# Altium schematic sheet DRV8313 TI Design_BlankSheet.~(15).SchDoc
size 431 x 279 mm; Date: Not shown in title block; ApprovedBy: Not shown in title block; CheckedBy: Not shown in title block; Author: Not shown in title block; CompanyName: Not shown in title block; Engineer: Not shown in title block; Organization: Not shown in title block; Address1: Not shown in title block; Address2: Not shown in title block; Address3: Not shown in title block; Address4: Not shown in title block; DocumentNumber: 1; Revision: Use project parameter SCH_Rev; SheetNumber: 2; SheetTotal: 3; PageSetup: Record=PageOptions¦CenterHorizontal=True¦CenterVertical=True¦PrintScale=1.00¦XCorrection=1.00¦YCorrection=1.00¦PrintKind=0¦BorderSize=5000000¦LeftOffset=0¦BottomOffset=0¦Orientation=2¦PaperLength=1000¦PaperWidth=1000¦Scale=100¦PaperSource=15¦PrintQuality=600¦MediaType=1¦DitherType=10¦PaperKind=Letter¦PrintScaleMode=1
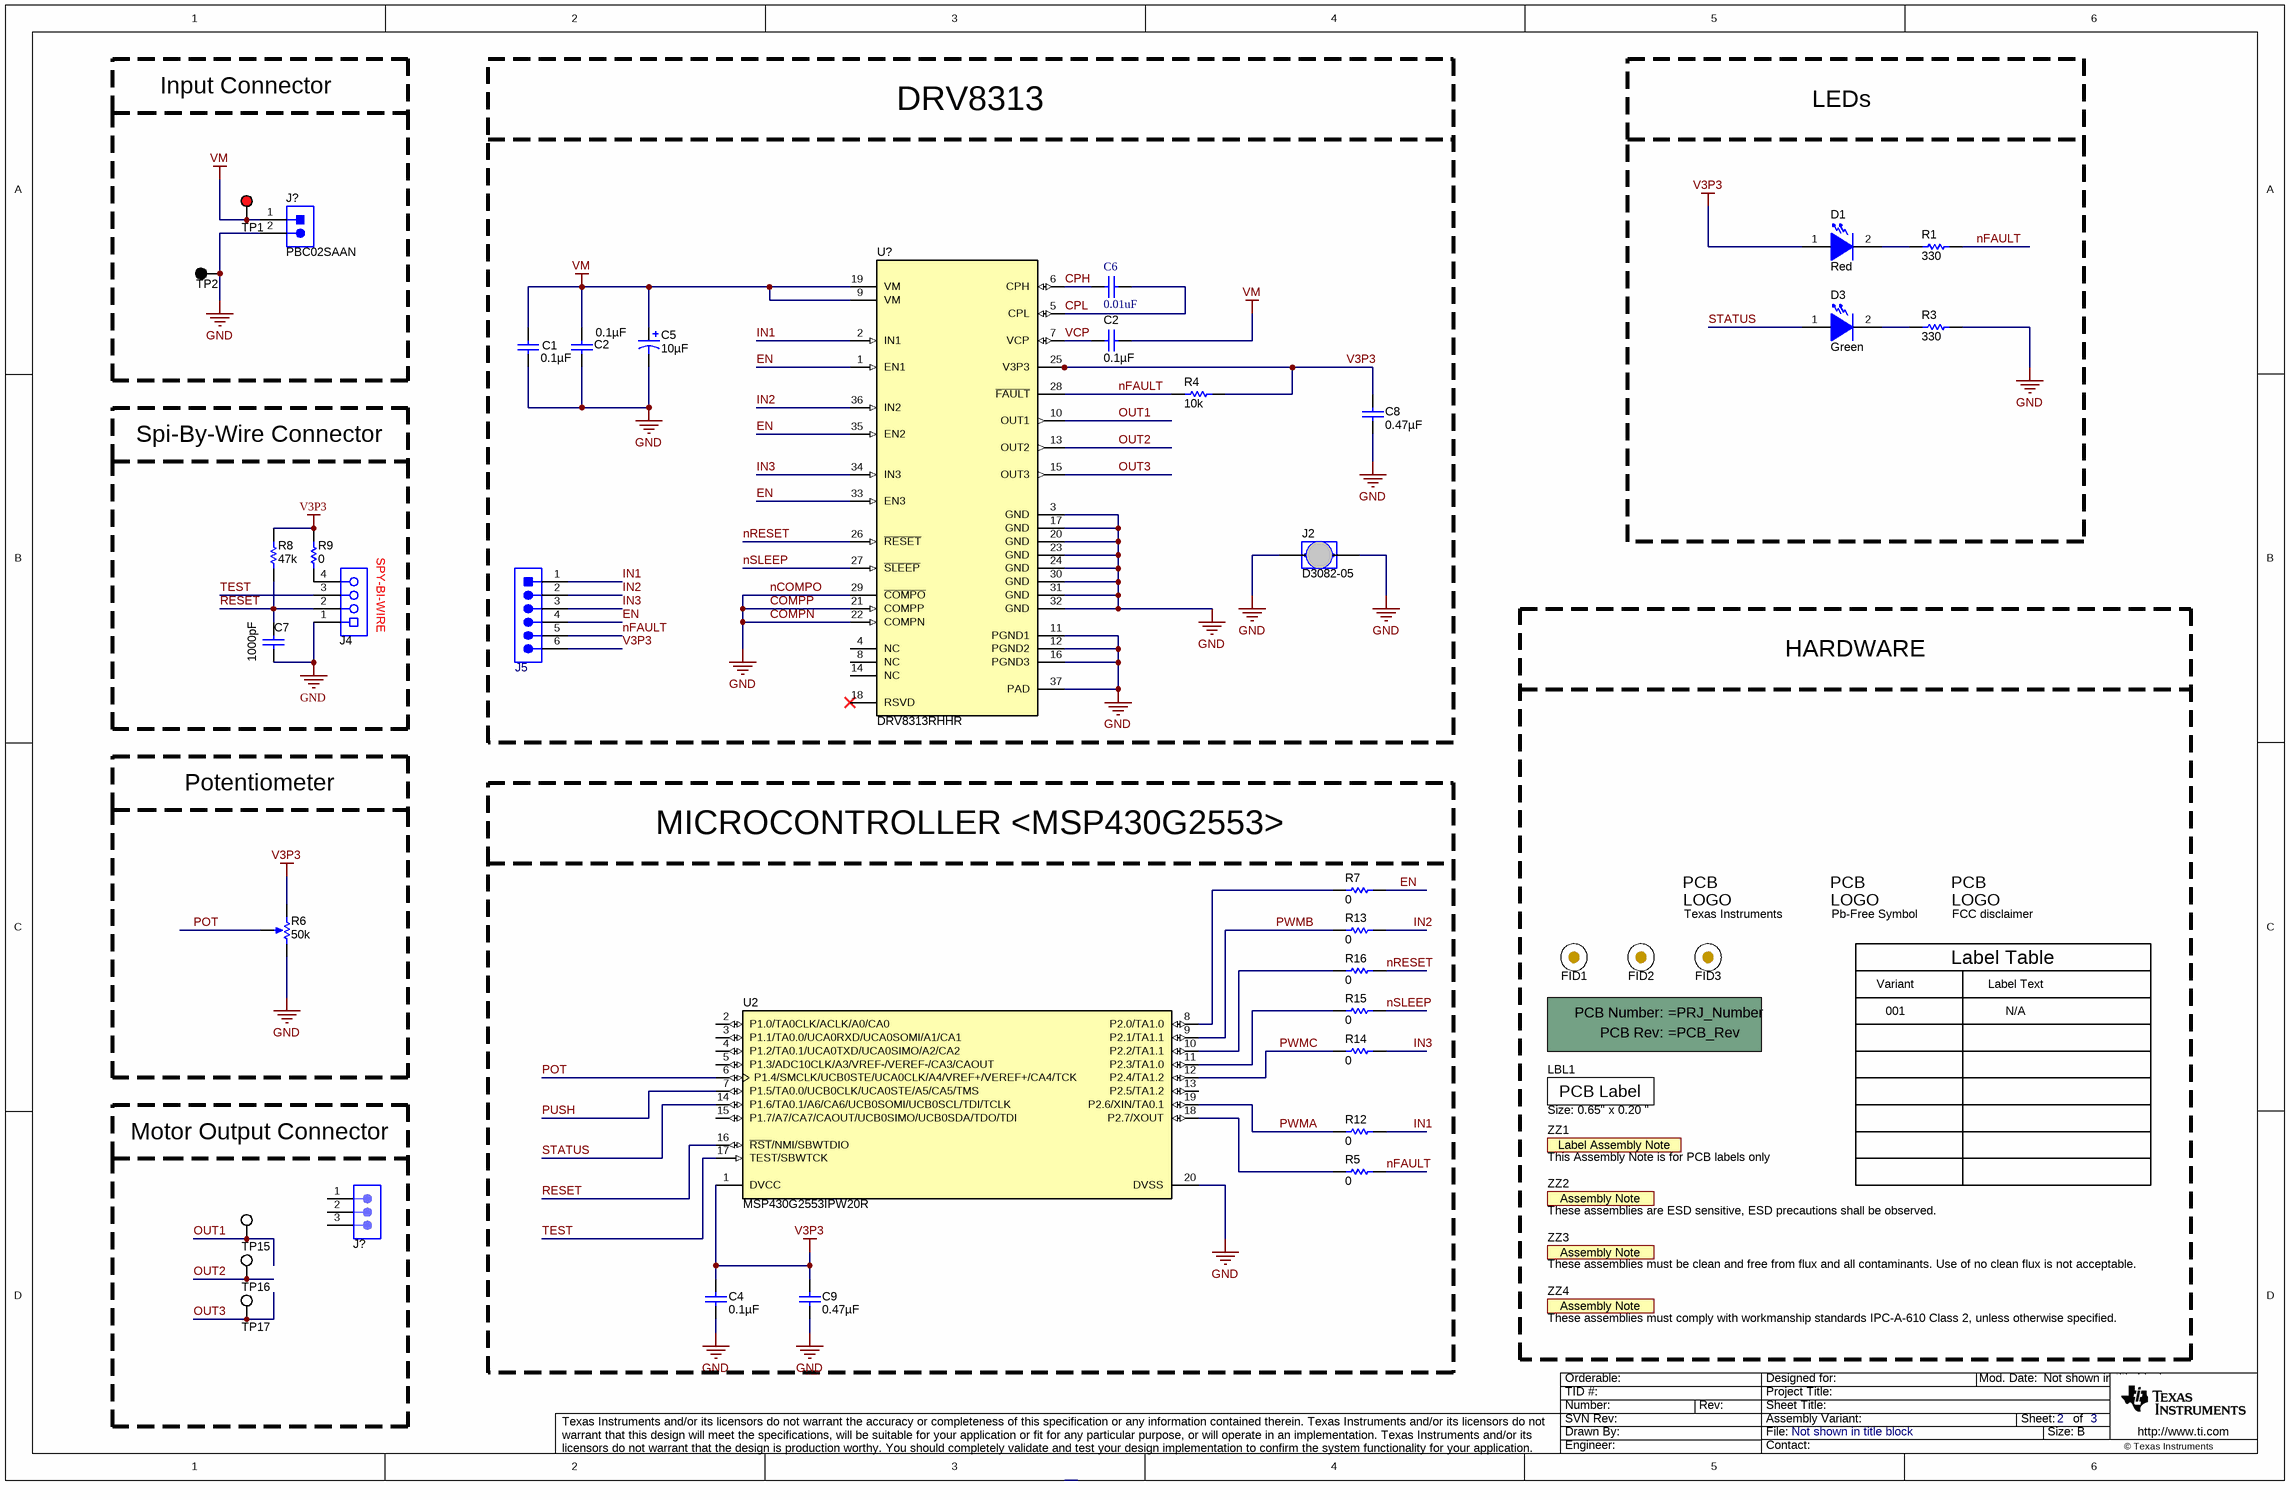
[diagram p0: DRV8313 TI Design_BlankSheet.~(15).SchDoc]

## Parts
(Parts that share a designator on the sheet are numbered #1, #2 ... from top to bottom, then left to right.)
!PCB  Printed Circuit Board  (value not drawn)  (mechanical)
C1  ValueDisplayed: 0.1µF  [0805_HV]  (hidden comment: C2012X5R2A104K125AA)
C2#1  ValueDisplayed: 0.1µF  [0805_HV]  (hidden comment: C2012X5R2A104K125AA)
C2#2  ValueDisplayed: 0.1µF  [0805_HV]  (hidden comment: C2012X5R2A104K125AA)
C4  ValueDisplayed: 0.1µF  [0603L]  (hidden comment: C0603C104K8RACTU)
C5  ValueDisplayed: 10µF  [SM_RADIAL_D8]  (hidden comment: EEE-FK1K100XP)
C6  0.01uF  [0603]
C7  ValueDisplayed: 1000pF  [0603L]  (hidden comment: GRM188R71C102KA01D)
C8  ValueDisplayed: 0.47µF  [0603]  (hidden comment: GCM188R71C474KA55D)
C9  ValueDisplayed: 0.47µF  [0603]  (hidden comment: GCM188R71C474KA55D)
D1  value Red  [LED_LTST-C170_Red]  (hidden comment: LTST-C170KRKT)
D3  value Green  [LTST-C170KGKT_Green]  (hidden comment: LTST-C170KGKT)
FID1  Fiducial  [Fiducial10-20]  (value not drawn)
FID2  Fiducial  [Fiducial10-20]  (value not drawn)
FID3  Fiducial  [Fiducial10-20]  (value not drawn)
J2  D3082-05  [Harwin_D3082-05]
J4  851-43-004-20-001000  [CONN_851-43-004-20-001000]  (value not drawn)
J5  PEC06SAAN  [Sullins_PEC06SAAN]  (value not drawn)
J?#1  PBC02SAAN  [Sullins_PBC02SAAN]
J?#2  PBC03SAAN  [PBC03SAAN]  (value not drawn)
LBL1  Size: 0.65" x 0.20 "  [Label_650x200]
Logo1  Texas Instruments  [TI_Stacked_Overlay_Small]  (no BOM)
Logo2  Pb-Free Symbol  [Pb-Free_Overlay_Small]  (no BOM)
Logo3  FCC disclaimer  [FCC_disclaimer]  (no BOM)
R1  ValueDisplayed: 330  [0603]  (hidden comment: CRCW0603330RJNEA)
R3  ValueDisplayed: 330  [0603]  (hidden comment: CRCW0603330RJNEA)
R4  ValueDisplayed: 10k  [0805_HV]  (hidden comment: CRCW080510K0JNEA)
R5  ValueDisplayed: 0  [0805_HV]  (hidden comment: ERJ-6GEY0R00V)
R6  value 50k  [Bourns_3352T]  (hidden comment: 3352T-1-503LF)
R7  ValueDisplayed: 0  [0805_HV]  (hidden comment: ERJ-6GEY0R00V)
R8  value 47k  [0603L]  (hidden comment: CRCW060347K0JNEA)
R9  value 0  [0603L]  (hidden comment: CRCW06030000Z0EA)
R12  ValueDisplayed: 0  [0805_HV]  (hidden comment: ERJ-6GEY0R00V)
R13  ValueDisplayed: 0  [0805_HV]  (hidden comment: ERJ-6GEY0R00V)
R14  ValueDisplayed: 0  [0805_HV]  (hidden comment: ERJ-6GEY0R00V)
R15  ValueDisplayed: 0  [0805_HV]  (hidden comment: ERJ-6GEY0R00V)
R16  ValueDisplayed: 0  [0805_HV]  (hidden comment: ERJ-6GEY0R00V)
TP1  5000  [Keystone5000]  (value not drawn)
TP2  5001  [Keystone5001]  (value not drawn)
TP15  5002  [Keystone5002]  (value not drawn)
TP16  5002  [Keystone5002]  (value not drawn)
TP17  5002  [Keystone5002]  (value not drawn)
U2  MSP430G2553IPW20R  [PW0020A_N]
U?  DRV8313RHHR  [RHH0036C]
ZZ1  This Assembly Note is for PCB labels only  [AssemblyNoteLabel]  (no BOM)
ZZ2  These assemblies are ESD sensitive, ESD precautions shall be observed.  [AssemblyNote]  (no BOM)
ZZ3  These assemblies must be clean and free from flux and all contaminants. Use of no clean flux is not acceptable.  [AssemblyNote]  (no BOM)
ZZ4  These assemblies must comply with workmanship standards IPC-A-610 Class 2, unless otherwise specified.  [AssemblyNote]  (no BOM)

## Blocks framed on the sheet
DRV8313: C1 C2#1 C2#2 C5 C6 C8 J2 J5 R4 U?
SPY-BI-WIRE: C7 J4 R8 R9
HARDWARE: !PCB FID1-FID3 LBL1 Logo1-Logo3 ZZ1-ZZ4

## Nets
COMPN: C1.1 C2#2.2 C4.2 C5.2(-) C7.2 C8.2 C9.2 J2.1 J2.2 J4.1 J?#1.2 R3.2 R6.3(CW) TP2.1 U2.20(DVSS) U?.3(GND) U?.11(PGND1) U?.12(PGND2) U?.16(PGND3) U?.17(GND) U?.20(GND) U?.21(COMPP) U?.22(COMPN) U?.23(GND) U?.24(GND) U?.29(~{COMPO}) U?.30(GND) U?.31(GND) U?.32(GND) U?.37(PAD)  [also labelled COMPP, GND, nCOMPO]
V3P3: C4.1 C8.1 C9.1 D1.1(A) J5.6 R4.2 R6.1(CCW) R8.2 R9.2 U2.1(DVCC) U?.25(V3P3)
VM: C1.2 C2#1.2 C2#2.1 C5.1(+) J?#1.1 TP1.1 U?.9(VM) U?.19(VM)
CPH: C6.2 U?.6(CPH)
CPL: C6.1 U?.5(CPL)
EN: J5.4 R7.2 U?.1(EN1) U?.33(EN3) U?.35(EN2)
IN1: J5.1 R12.2 U?.2(IN1)
IN2: J5.2 R13.2 U?.36(IN2)
IN3: J5.3 R14.2 U?.34(IN3)
nFAULT: J5.5 R1.2 R4.1 R5.2 U?.28(~{FAULT})
nRESET: R16.2 U?.26(~{RESET})
nSLEEP: R15.2 U?.27(~{SLEEP})
OUT1: TP15.1 U?.10(OUT1)
OUT2: TP16.1 U?.13(OUT2)
OUT3: TP17.1 U?.15(OUT3)
POT: R6.2(WIPER) U2.6(P1.4/SMCLK/UCB0STE/UCA0CLK/A4/VREF+/VEREF+/CA4/TCK)
PUSH: U2.7(P1.5/TA0.0/UCB0CLK/UCA0STE/A5/CA5/TMS)
PWMA: R12.1 U2.19(P2.6/XIN/TA0.1)
PWMB: R13.1 U2.9(P2.1/TA1.1)
PWMC: R14.1 U2.12(P2.4/TA1.2)
RESET: C7.1 J4.2 R8.1 U2.16(~{RST}/NMI/SBWTDIO)
STATUS: D3.1(A) U2.14(P1.6/TA0.1/A6/CA6/UCB0SOMI/UCB0SCL/TDI/TCLK)
TEST: J4.3 U2.17(TEST/SBWTCK)
VCP: C2#1.1 U?.7(VCP)
NetD1_2: D1.2(K) R1.1
NetD3_2: D3.2(K) R3.1
NetJ4_4: J4.4 R9.1
NetR5_1: R5.1 U2.18(P2.7/XOUT)
NetR7_1: R7.1 U2.8(P2.0/TA1.0)
NetR15_1: R15.1 U2.11(P2.3/TA1.0)
NetR16_1: R16.1 U2.10(P2.2/TA1.1)

Not connected (* = marked no-connect by the designer): J?#2 1 2 3; U2 2(P1.0/TA0CLK/ACLK/A0/CA0) 3(P1.1/TA0.0/UCA0RXD/UCA0SOMI/A1/CA1) 4(P1.2/TA0.1/UCA0TXD/UCA0SIMO/A2/CA2) 5(P1.3/ADC10CLK/A3/VREF-/VEREF-/CA3/CAOUT) 13(P2.5/TA1.2) 15(P1.7/A7/CA7/CAOUT/UCB0SIMO/UCB0SDA/TDO/TDI); U? 4(NC) 8(NC) 14(NC) 18(RSVD)*

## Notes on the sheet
- Input Connector
- LEDs
- Spi-By-Wire Connector
- Potentiometer
- MICROCONTROLLER <MSP430G2553>
- Label Table
- Variant
- 001
- Label Text
- N/A
- Motor Output Connector

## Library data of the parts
!PCB = PCB: Manufacturer: Any; SymbolCreator: a0412235
C1 C2#1 C2#2 = C2012X5R2A104K125AA: CAP, CERM, 0.1 µF, 100 V, +/- 10%, X5R, 0805; Manufacturer: TDK; Polarized: N; CompType: Capacitor; Value: 0.1uF; U/M: EA; Cap_F: 0.0000001; Tolerance_%: 10; ESR_ohm: 0.020726; Value1: 0.020726 ohm; VDC_V: 100; Value2: 100V; IRMS_A: 1.456; TaMin_C: -55; TaMax_C: 85; Cap_Case: 0805; SizeArea_mm2: 2.5; SizeAreaWB_mm2: 6.75; SizeX_mm: 2; SizeY_mm: 1.25; SizeZ_mm: 1.45; AEC Category: Q200
C4 = C0603C104K8RACTU: CAP, CERM, 0.1 µF, 10 V, +/- 10%, X7R, 0603; Manufacturer: Kemet; Polarized: N; CompType: Capacitor; Value: 0.1uF; U/M: EA; Cap_F: 0.0000001; Tolerance_%: 10; Value1: Unknown; Value2: 10V; TaMin_C: -55; TaMax_C: 125; Cap_Case: 0603; AEC Category: Q200
C5 = EEE-FK1K100XP: CAP, AL, 10 µF, 80 V, +/- 20%, 2.4 ohm, AEC-Q200 Grade 2, SMD; Manufacturer: Panasonic; Polarized: Y; CompType: Capacitor; Value: 10uF; U/M: EA; Cap_F: 0.00001; Tolerance_%: 20; Value1: 2.4 ohm; VDC_V: 80; Value2: 80V; ESR_ohm: 2.4; IRMS_A: 0.06; TaMin_C: -55; TaMax_C: 105; Cap_Case: D8; SizeAreaWB_mm2: 84.28; SizeArea_mm2: 51.48; SizeX_mm: 7.8; SizeY_mm: 6.6; SizeZ_mm: 7.7; AEC Category: Q200; AEC Grade: 2
C6 = Cap: Capacitor; Manufacturer: Murata; MFG Part Number: GCM188R72A103KA37D; Value: .01uF; Cap Voltage: 100V
C7 = GRM188R71C102KA01D: CAP, CERM, 1000 pF, 16 V, +/- 10%, X7R, 0603; Manufacturer: MuRata; Polarized: N; CompType: Capacitor; Value: 1000pF; U/M: EA; Cap_F: 0.000000001; Tolerance_%: 10; Value1: Unknown; VDC_V: 16; Value2: 16V; TaMin_C: -55; TaMax_C: 125; Cap_Case: 0603; AEC Category: Q200
C8 C9 = GCM188R71C474KA55D: CAP, CERM, 0.47 µF, 16 V, +/- 10%, X7R, AEC-Q200 Grade 1, 0603; Manufacturer: MuRata; Polarized: N; CompType: Capacitor; Value: 0.47uF; U/M: EA; Cap_F: 0.00000047; Tolerance_%: 10; Value1: Unknown; VDC_V: 16; Value2: 16V; TaMin_C: -55; TaMax_C: 125; SizeArea_mm2: 1.28; SizeAreaWB_mm2: 4.68; SizeX_mm: 1.6; SizeY_mm: 0.8; SizeZ_mm: 1; AEC Category: Q200; AEC Qualified: Y
D1 = LTST-C170KRKT: LED, Red, SMD; Manufacturer: Lite-On; Type: AlInGaP; Vf_V: 2; Value2: 2V; Io_A: 0.02; Value1: W; SizeAreaWB_mm2: 6.75; SizeArea_mm2: 2.5; SizeY_mm: 1.25; SizeZ_mm: 1.2; U/M: EA
D3 = LTST-C170KGKT: LED, Green, SMD; Manufacturer: Lite-On; Type: AlInGaP; Vf_V: 2; Value2: 2V; Io_A: 0.02; Value1: W; U/M: EA
FID1-FID3 = Fiducial: Fiducial mark.  There is nothing to buy or mount.; SymbolCreator: codlsc
J2 = D3082-05: 1mm Uninsulated Shorting Plug, 10.16mm spacing, TH; Manufacturer: Harwin; SymbolCreator: a0799628; CompType: Jumper Wire
J4 = 851-43-004-20-001000: SOCKET .050" GRID SIP 4 POS R/A, TH; Manufacturer: Mill-Max; SymbolCreator: a0411947; CompType: Header
J5 = PEC06SAAN: Header, 100mil, 6x1, Tin, TH; Manufacturer: Sullins Connector Solutions; SymbolCreator: a0412235; U/M: EA
J?#1 = PBC02SAAN: Header, 100mil, 2x1, Gold, TH; Manufacturer: Sullins Connector Solutions; SymbolCreator: a0412235; Pitch_mm: 2.54; Gender: Male; Shrouded: N; Row_Count: 1; Current_A: 3; Voltage_V: 1800; Cert_UL: Y
J?#2 = PBC03SAAN: Header, 100mil, 3x1, Gold, TH; Manufacturer: Sullins Connector Solutions
LBL1 = THT-14-423-10: Thermal Transfer Printable Labels, 0.650" W x 0.200" H - 10,000 per roll; Manufacturer: Brady; SymbolCreator: a0412235; CompType: Label
Logo1 = TI_Logo: Texas Instrument Corporate Signature; SymbolCreator: codlsc
Logo2 = Pb-Free: SymbolCreator: a0412235
Logo3 = FCC_disclaimer: SymbolCreator: codlsc
R1 R3 = CRCW0603330RJNEA: RES, 330, 5%, 0.1 W, 0603; Manufacturer: Vishay-Dale; CompType: Resistor; Value: 330; Value_Code: 330R; Tolerance_%: 5; Power_W: 0.1; Value2: 0.1W; VDC_V: 75; TempCo: 200 ppm/C; SizeArea_mm2: 1.28; SizeX_mm: 1.6; SizeY_mm: 0.8; SizeZ_mm: 1; EIA_Code: E24; U/M: EA; AEC Category: Q200
R4 = CRCW080510K0JNEA: RES, 10 k, 5%, 0.125 W, 0805; Manufacturer: Vishay-Dale; CompType: Resistor; Value: 10k; Res_ohm: 10000; Value_Code: 10k0; Tolerance_%: 5; Power_W: 0.125; Value2: 0.125W; VDC_V: 150; TempCo: 200 ppm/C; SizeArea_mm2: 2.5; SizeX_mm: 2; SizeY_mm: 1.25; SizeZ_mm: 1.45; EIA_Code: E24; U/M: EA; AEC Category: Q200
R5 R7 R12-R16 = ERJ-6GEY0R00V: RES, 0, 5%, 0.125 W, 0805; Manufacturer: Panasonic; CompType: Resistor; Value: 0; Value_Code: 0000; Tolerance_%: 5; Power_W: 0.125; Value2: 0.125W; VDC_V: 150; TempCo: 600 ppm/C; SizeArea_mm2: 2.5; SizeX_mm: 2; SizeY_mm: 1.25; SizeZ_mm: 1.45; EIA_Code: E24; U/M: EA; AEC Category: Q200
R6 = 3352T-1-503LF: Trimming Potentiometer, 50K, 0.5W, TH; Manufacturer: Bourns; Sim Note: Enter the Resistance value and the set point into parameter fields.; SymbolCreator: a0412235; CompType: Trimmer
R8 = CRCW060347K0JNEA: RES, 47 k, 5%, 0.1 W, 0603; Manufacturer: Vishay-Dale; CompType: Resistor; Res_ohm: 47000; Value_Code: 47k0; Tolerance_%: 5; Power_W: 0.1; Value2: 0.1W; VDC_V: 75; TempCo: 200 ppm/C; EIA_Code: E24; U/M: EA; AEC Category: Q200
R9 = CRCW06030000Z0EA: RES, 0, 5%, 0.1 W, 0603; Manufacturer: Vishay-Dale; CompType: Resistor; Value_Code: 0000; Tolerance_%: 5; Power_W: 0.1; Value2: 0.1W; VDC_V: 75; TempCo: 200 ppm/C; EIA_Code: E24; U/M: EA; AEC Category: Q200
TP1 = 5000: Test Point, Miniature, Red, TH; Manufacturer: Keystone; CompType: Test Point Loop; ContactFinish: Silver
TP2 = 5001: Test Point, Miniature, Black, TH; Manufacturer: Keystone; CompType: Test Point Loop; ContactFinish: Silver
TP15-TP17 = 5002: Test Point, Miniature, White, TH; Manufacturer: Keystone; CompType: Test Point Loop; ContactFinish: Silver
U2 = MSP430G2553IPW20R: 16 MHz Mixed Signal Microcontroller with 16 KB Flash, 512 B SRAM and 24 GPIOs, -40 to 85 degC, 20-pin SOP (PW), Green (RoHS & no Sb/Br); Alternate Manufacturer: Texas Instruments; Alternate PartNumber: Equivalent; ADC: 10-bit SAR; ADC Channels: 8; Brown Out Reset: Yes; Flash(KB): 16; GPIO: 24; Pin/Package: 0DIESALE, 0WAFERSALE, 20PDIP, 20TSSOP, 28TSSOP, 32QFN; SRAM(B): 512; SubFamily: Value Line; Timers - 16-bit: 2; USCI_A (UART/LIN/IrDA/SPI): 1
U? = DRV8313RHHR: 2.5-A Triple 1/2-H Bridge Driver, RHH0036C; Manufacturer: Texas Instruments; SymbolCreator: Altium; SizeArea_mm2: 36; SizeAreaWB_mm2: 64; SizeX_mm: 6; SizeZ_mm: 1; CompType: IC; U/M: EA
ZZ1 = AssemblyNoteLabel: SymbolCreator: a0412235
ZZ2-ZZ4 = AssemblyNote: SymbolCreator: codlsc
